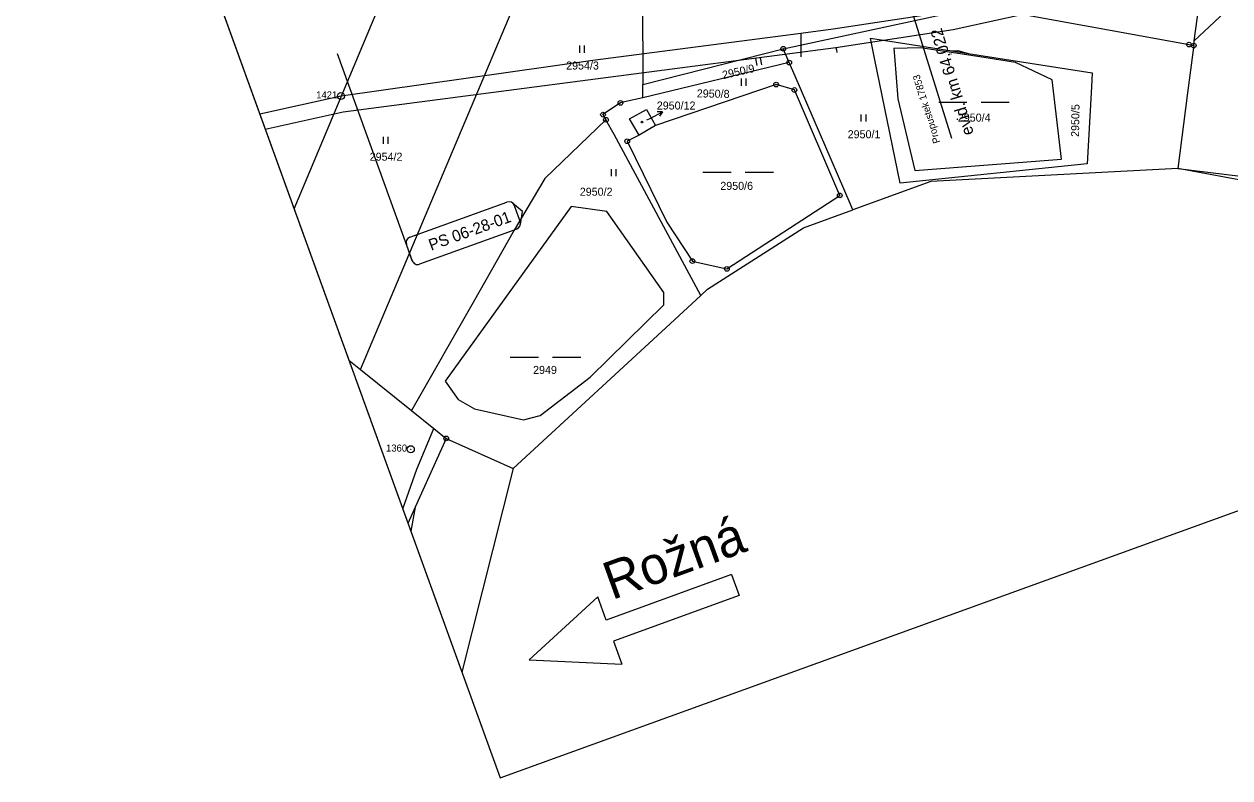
# Model space of a CAD drawing. Extents: x -620552 to -620056, y -1123312 to -1122890.
# Drawn here: x -620552.1 to -620295.9, y -1123311.9 to -1123151.7 of the extents above; entities that cross this region are included whole.
import ezdxf

# ---------------------------------------------------------------- set-up
doc = ezdxf.new("R2010")
doc.units = 0
for name, color, linetype in [('bubliny', 7, 'Continuous'), ('EXP_kolej_podélný profil_POPIS', 7, 'Continuous'), ('Hranice parcel', 7, 'Continuous'), ('Parcelní čísla', 7, 'Continuous'), ('Pop  PČ popisy', 7, 'Continuous'), ('Rámečky', 7, 'Continuous'), ('Rámečky-tisk', 7, 'Continuous'), ('VAS vodovod', 7, 'Continuous'), ('Vnitřní kresba', 7, 'Continuous'), ('Vrstva 19', 7, 'Continuous'), ('Značky bodu BP', 7, 'Continuous'), ('Značky budov', 7, 'Continuous'), ('Značky kultur', 7, 'Continuous')]:
    doc.layers.add(name, color=color, linetype=linetype)

msp = doc.modelspace()

# ---------------------------------------------------------------- linework, layer by layer
at = {"layer": 'bubliny'}
msp.add_line((-620485.58, -1123158), (-620469.65, -1123202), dxfattribs=at)
for points in [[(-620470.16, -1123197), (-620449.53, -1123189.53)], [(-620446.66, -1123194.32), (-620446.2, -1123191.56), (-620448.32, -1123189.75)], [(-620447.96, -1123190.26), (-620446.72, -1123193.7)], [(-620447.96, -1123190.26), (-620446.72, -1123193.7)], [(-620447.45, -1123195.26), (-620468.09, -1123202.73)], [(-620469.65, -1123202), (-620470.89, -1123198.56)]]:
    msp.add_lwpolyline(points, dxfattribs=at)
for centre, start, end in [((-620449.11, -1123190.67), 19.9058, 109.9058), ((-620449.11, -1123190.67), 19.9058, 49.4576), ((-620447.87, -1123194.11), 289.9058, 19.9058), ((-620447.87, -1123194.11), 350.3539, 19.9058), ((-620469.75, -1123198.14), 109.9058, 199.9058), ((-620468.5, -1123201.58), 199.9058, 289.9058)]:
    msp.add_arc(centre, 1.22, start, end, dxfattribs=at)
at = {"layer": 'EXP_kolej_podélný profil_POPIS'}
for p, q in [((-620401.83, -1123268.67), (-620428.48, -1123278.32)), ((-620401.83, -1123268.67), (-620400.22, -1123273.13)), ((-620430.25, -1123273.42), (-620444.8, -1123286.75)), ((-620428.48, -1123278.32), (-620430.25, -1123273.42)), ((-620400.22, -1123273.13), (-620426.86, -1123282.78)), ((-620426.86, -1123282.78), (-620425.09, -1123287.68)), ((-620444.8, -1123286.75), (-620425.09, -1123287.68))]:
    msp.add_line(p, q, dxfattribs=at)
at = {"layer": 'Hranice parcel'}
for p, q in [((-620303.5, -1123155.32), (-620298.49, -1123117.9)), ((-620420.8, -1123130.97), (-620420.66, -1123164.55)), ((-620480.65, -1123225.1), (-620442.33, -1123134.4)), ((-620494.75, -1123190.98), (-620473.69, -1123140.72)), ((-620303.63, -1123156.28), (-620303.5, -1123155.32)), ((-620420.66, -1123164.55), (-620390.82, -1123156.97)), ((-620389.56, -1123159.9), (-620390.82, -1123156.97)), ((-620389.56, -1123159.9), (-620420.67, -1123167.38)), ((-620420.67, -1123167.38), (-620420.66, -1123164.55)), ((-620304.97, -1123166.33), (-620307.01, -1123182.39)), ((-620417.95, -1123173.25), (-620421.43, -1123175.35)), ((-620307.01, -1123182.39), (-620259.01, -1123188.34)), ((-620259.81, -1123191.23), (-620307.01, -1123182.39)), ((-620483.1, -1123223.13), (-620480.65, -1123225.1)), ((-620483.1, -1123223.13), (-620480.65, -1123225.1)), ((-620480.65, -1123225.1), (-620469.81, -1123233.8)), ((-620480.65, -1123225.1), (-620469.81, -1123233.8)), ((-620469.81, -1123233.8), (-620465.05, -1123237.62)), ((-620469.81, -1123233.8), (-620465.05, -1123237.62)), ((-620465.05, -1123237.62), (-620462.42, -1123239.73)), ((-620465.05, -1123237.62), (-620462.42, -1123239.73)), ((-620462.42, -1123239.73), (-620448.18, -1123246.14)), ((-620448.18, -1123246.14), (-620459.12, -1123289.37)), ((-620469, -1123254.37), (-620470.55, -1123257.81)), ((-620469, -1123254.37), (-620470.55, -1123257.81))]:
    msp.add_line(p, q, dxfattribs=at)
for points in [[(-620267.31, -1123105.13), (-620271.09, -1123121.69), (-620283, -1123136.04), (-620303.5, -1123155.32)], [(-620390.82, -1123156.97), (-620349.09, -1123147.99), (-620304.63, -1123156.08), (-620303.63, -1123156.28)], [(-620372.3, -1123154.73), (-620354.98, -1123157.43), (-620353.71, -1123157.32)], [(-620353.71, -1123157.32), (-620351.54, -1123157.97), (-620325.21, -1123162.08), (-620325.37, -1123165.05), (-620326.24, -1123181.42), (-620366.02, -1123185.52), (-620371.44, -1123158.94), (-620372.3, -1123154.73)], [(-620366.46, -1123167.58), (-620362.9, -1123182.84), (-620331.75, -1123180.43), (-620333.71, -1123163.55), (-620341.51, -1123159.88), (-620349.04, -1123158.72), (-620356.47, -1123157.57), (-620361.65, -1123156.77), (-620367.33, -1123156.94), (-620367.2, -1123158.55), (-620366.46, -1123167.58)], [(-620303.63, -1123156.28), (-620303.83, -1123157.77), (-620304.97, -1123166.33)], [(-620376.06, -1123191.18), (-620376.64, -1123189.84), (-620388.32, -1123162.77), (-620389.56, -1123159.9)], [(-620421.43, -1123175.35), (-620423.97, -1123176.6), (-620415.57, -1123193.78), (-620410.14, -1123202.09), (-620408.92, -1123202.36), (-620402.8, -1123203.74), (-620378.83, -1123188.12), (-620388.45, -1123165.73), (-620392.34, -1123164.57), (-620417.95, -1123173.25)], [(-620420.67, -1123167.38), (-620424.53, -1123168.26), (-620425.41, -1123168.46), (-620429.12, -1123170.97), (-620428.51, -1123172.06)], [(-620421.43, -1123175.35), (-620423.5, -1123171.89), (-620419.89, -1123169.88), (-620417.95, -1123173.25)], [(-620428.51, -1123172.06), (-620441.5, -1123184.51), (-620447.97, -1123195.52), (-620456.72, -1123210.85), (-620469.81, -1123233.8)], [(-620408.37, -1123209.4), (-620426.77, -1123175.15), (-620428.51, -1123172.06)], [(-620307.01, -1123182.39), (-620359.5, -1123185.17), (-620376.06, -1123191.18)], [(-620459.9, -1123231.5), (-620456.4, -1123233.47), (-620446.03, -1123235.78), (-620442.49, -1123234.88), (-620431.86, -1123226.73), (-620416.2, -1123211.37), (-620416.17, -1123208.77), (-620428.32, -1123191.51), (-620435.86, -1123190.48), (-620462.66, -1123227.61), (-620459.9, -1123231.5)], [(-620408.37, -1123209.4), (-620406.9, -1123208.04), (-620386.54, -1123194.99), (-620376.06, -1123191.18)], [(-620448.18, -1123246.14), (-620413, -1123213.67), (-620408.37, -1123209.4)], [(-620471.67, -1123254.71), (-620468.69, -1123246.27), (-620465.05, -1123237.62)], [(-620462.42, -1123239.73), (-620467.02, -1123249.97), (-620469, -1123254.37)], [(-620462.42, -1123239.73), (-620467.02, -1123249.97), (-620469, -1123254.37)], [(-620469, -1123254.37), (-620469.96, -1123259.44)]]:
    msp.add_lwpolyline(points, dxfattribs=at)
at = {"layer": 'Pop  PČ popisy'}
for p, q in [((-620419.13, -1123171.75), (-620416.46, -1123170.39)), ((-620416.46, -1123170.39), (-620417.58, -1123170.4)), ((-620416.46, -1123170.39), (-620417.12, -1123171.29)), ((-620419.81, -1123172.09), (-620419.13, -1123171.75))]:
    msp.add_line(p, q, dxfattribs=at)
at = {"layer": 'Rámečky'}
msp.add_lwpolyline([(-620552.1, -1123032.6), (-620450.98, -1123311.85), (-620056.07, -1123168.86)], dxfattribs=at)
at = {"layer": 'Rámečky-tisk'}
msp.add_line((-620552.1, -1123032.6), (-620450.98, -1123311.85), dxfattribs=at)
msp.add_lwpolyline([(-620450.98, -1123311.85), (-620056.07, -1123168.86), (-620157.19, -1122889.6), (-620552.1, -1123032.6)], dxfattribs=at)
at = {"layer": 'VAS vodovod'}
for points in [[(-620149.01, -1123008.86), (-620153.26, -1123021.35), (-620170.32, -1123042.17), (-620174.28, -1123046.08), (-620197.72, -1123068.73), (-620228.79, -1123097.03), (-620270.23, -1123119.97), (-620279.98, -1123125.39), (-620293.71, -1123133.06), (-620298.47, -1123135.79), (-620300.47, -1123136.51), (-620304.69, -1123137.51), (-620306.42, -1123137.92), (-620355.45, -1123149.02), (-620380.2, -1123152.84), (-620387.1, -1123153.74), (-620431.25, -1123159.48), (-620484.75, -1123167.02), (-620502.03, -1123170.86)], [(-620143.62, -1123010.63), (-620143.76, -1123012.48), (-620147.75, -1123024.43), (-620148.88, -1123025.86), (-620151.68, -1123028.7), (-620167.48, -1123044.99), (-620171.49, -1123048.94), (-620194.98, -1123071.65), (-620226.44, -1123100.3), (-620258.1, -1123117.83), (-620268.29, -1123123.47), (-620278.03, -1123128.88), (-620291.74, -1123136.54), (-620296.78, -1123139.43), (-620299.32, -1123140.35), (-620305.52, -1123141.82), (-620338.85, -1123149.47), (-620354.7, -1123152.95), (-620379.64, -1123156.8), (-620430.73, -1123163.45), (-620484.29, -1123170.42), (-620500.86, -1123174.1)], [(-620387.1, -1123153.74), (-620387.07, -1123154.39), (-620387.1, -1123158.69)], [(-620379.64, -1123156.8), (-620379.54, -1123157.18), (-620379.42, -1123157.73)]]:
    msp.add_lwpolyline(points, dxfattribs=at)
at = {"layer": 'Vnitřní kresba'}
msp.add_line((-620354.98, -1123157.43), (-620351.54, -1123157.97), dxfattribs=at)
at = {"layer": 'Vrstva 19'}
msp.add_line((-620355.01, -1123176.04), (-620372.81, -1123118.74), dxfattribs=at)
at = {"layer": 'Značky bodu BP'}
for centre, radius in [((-620304.63, -1123156.08), 0.5), ((-620390.82, -1123156.97), 0.5), ((-620390.82, -1123156.97), 0.0303), ((-620304.63, -1123156.08), 0.0303), ((-620303.63, -1123156.28), 0.5), ((-620303.63, -1123156.28), 0.0303), ((-620389.56, -1123159.9), 0.5), ((-620389.56, -1123159.9), 0.0303), ((-620392.34, -1123164.57), 0.5), ((-620392.34, -1123164.57), 0.0303), ((-620388.45, -1123165.73), 0.5), ((-620388.45, -1123165.73), 0.0303), ((-620484.79, -1123167.02), 0.75), ((-620484.79, -1123167.02), 0.03), ((-620425.41, -1123168.46), 0.5), ((-620425.41, -1123168.46), 0.0303), ((-620429.12, -1123170.97), 0.5), ((-620429.12, -1123170.97), 0.0303), ((-620428.51, -1123172.06), 0.5), ((-620428.51, -1123172.06), 0.0303), ((-620423.97, -1123176.6), 0.5), ((-620423.97, -1123176.6), 0.0303), ((-620378.83, -1123188.12), 0.5), ((-620378.83, -1123188.12), 0.0303), ((-620410.14, -1123202.09), 0.5), ((-620410.14, -1123202.09), 0.0303), ((-620402.8, -1123203.74), 0.5), ((-620402.8, -1123203.74), 0.0303), ((-620462.42, -1123239.73), 0.5), ((-620462.42, -1123239.73), 0.0303), ((-620469.96, -1123242.04), 0.75), ((-620469.96, -1123242.04), 0.03)]:
    msp.add_circle(centre, radius, dxfattribs=at)
at = {"layer": 'Značky budov'}
msp.add_circle((-620420.82, -1123172.55), 0.175, dxfattribs=at)
at = {"layer": 'Značky kultur'}
for p, q in [((-620434.06, -1123157.81), (-620434.06, -1123156.31)), ((-620433.06, -1123157.81), (-620433.06, -1123156.31)), ((-620396.39, -1123160.52), (-620396.62, -1123159.04)), ((-620395.4, -1123160.36), (-620395.63, -1123158.88)), ((-620399.71, -1123164.81), (-620399.71, -1123163.31)), ((-620398.71, -1123164.81), (-620398.71, -1123163.31)), ((-620357.8, -1123168.35), (-620351.8, -1123168.35)), ((-620348.8, -1123168.35), (-620342.8, -1123168.35)), ((-620374.24, -1123172.41), (-620374.24, -1123170.91)), ((-620373.24, -1123172.41), (-620373.24, -1123170.91)), ((-620475.78, -1123177.18), (-620475.78, -1123175.68)), ((-620474.78, -1123177.18), (-620474.78, -1123175.68)), ((-620427.33, -1123184.04), (-620427.33, -1123182.54)), ((-620426.33, -1123184.04), (-620426.33, -1123182.54)), ((-620407.9, -1123183.15), (-620401.9, -1123183.15)), ((-620398.9, -1123183.15), (-620392.9, -1123183.15)), ((-620448.85, -1123222.47), (-620442.85, -1123222.47)), ((-620439.85, -1123222.47), (-620433.85, -1123222.47))]:
    msp.add_line(p, q, dxfattribs=at)

# ---------------------------------------------------------------- texts
at = {"layer": 'bubliny'}
msp.add_text('PS 06-28-01', height=2.4384, rotation=19.9058, dxfattribs=at).set_placement((-620465.63, -1123199.9))
at = {"layer": 'EXP_kolej_podélný profil_POPIS'}
msp.add_text('Rožná', height=8, rotation=19.9058, dxfattribs=at).set_placement((-620427.21, -1123274.11))
at = {"layer": 'Parcelní čísla'}
for s, p in [('2954/3', (-620436.95, -1123161.38)), ('2950/12', (-620417.69, -1123169.88)), ('2950/4', (-620353.74, -1123172.45)), ('2950/1', (-620377.14, -1123175.98)), ('2954/2', (-620478.68, -1123180.75)), ('2950/2', (-620434.05, -1123188.19)), ('2950/6', (-620404.2, -1123186.94)), ('2949', (-620443.97, -1123226.04))]:
    msp.add_text(s, height=1.7, dxfattribs=at).set_placement(p)
for s, rotation, p in [('2950/9', 13, (-620403.57, -1123163.42)), ('2950/8', 359, (-620409.2, -1123167.29)), ('2950/5', 89, (-620328, -1123175.71))]:
    msp.add_text(s, height=1.7, rotation=rotation, dxfattribs=at).set_placement(p)
at = {"layer": 'Vrstva 19'}
for s, height, p in [('evid. km 64,022', 2.5, (-620350.32, -1123174.96)), ('Propustek 17853', 1.5, (-620357.48, -1123176.82))]:
    msp.add_text(s, height=height, rotation=107.0012, dxfattribs=at).set_placement(p)
at = {"layer": 'Značky bodu BP'}
for s, p in [('1421', (-620490.04, -1123167.52)), ('1360', (-620475.21, -1123242.54))]:
    msp.add_text(s, height=1.5, dxfattribs=at).set_placement(p)

doc.saveas('drawing.dxf')
